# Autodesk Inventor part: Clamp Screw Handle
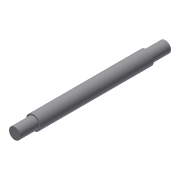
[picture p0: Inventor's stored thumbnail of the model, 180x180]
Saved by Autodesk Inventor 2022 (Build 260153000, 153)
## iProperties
Created: 2002-02
Part Number: Clamp Screw Handle
Document SubType Name: Modeling
Designer: ***
Density: 1 g/cm^3
Material: Generic
Mass: 7.51155 g
Surface Area: 32.9239 cm^2
Volume: 7.51155 cm^3
Appearance: Default
Control State: 0
Master: False
Checked Out: False
Shininess: 77.0
Length Units: 11269
Angle Units: 11279
Time Units: 11290
Mass Units: 11283
Length Display Precision: 3
Angle Display Precision: 2
Compacted: True
Density: 0.0
Volumn: 0.0
Area: 0.0
PropertySet Name: Model Information
Author: ***
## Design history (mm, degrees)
sketch "Sketch1"
  geometry: L1 (0, 105)-(4, 105); L2 (4, 105)-(4, 92); L3 (4, 92)-(5, 92); L4 (5, 92)-(5, 13); L5 (5, 13)-(4, 13); L6 (4, 13)-(4, 0); L7 (4, 0)-(0, 0); L8 (0, 0)-(0, 105)
  constraints: 16 end point, 5 parallel, 2 equal length, 1 collinear, 1 horizontal, 1 perpendicular
  dimensions: "d0" = 10 diameter of L4 L8; "d1" = 8 diameter of L2 L8; "d2" = 13 distance of L1.end L2.end; "d3" = 79 distance of L3.end L4.end
revolve "Revolution1" sketch "Sketch1" stored, may be unused: angle "d4" = 90 deg
body "Solid1"
